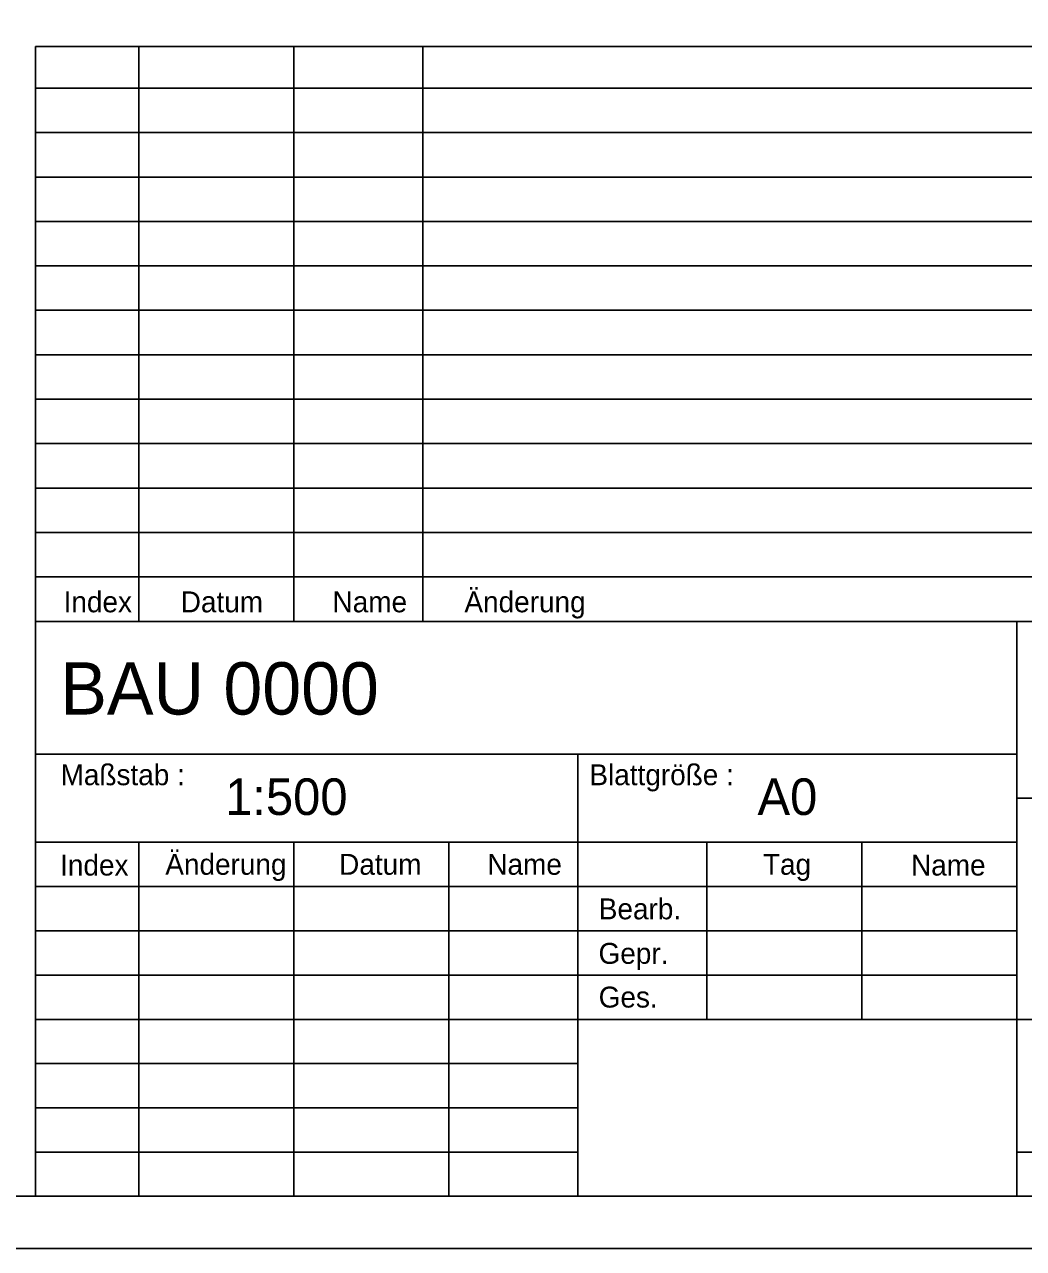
# Model space of a CAD drawing. Extents: x 0 to 594, y 0 to 420.
# Drawn here: x 502.5 to 550.3, y 0 to 58.5 of the extents above; entities that cross this region are included whole.
import ezdxf

# ---------------------------------------------------------------- set-up
doc = ezdxf.new("R2010")
doc.units = 0
doc.layers.add('90_Plankopf', color=7, linetype='Continuous')

msp = doc.modelspace()

# ---------------------------------------------------------------- linework, layer by layer
at = {"layer": '90_Plankopf'}
for p, q in [((503.06, 29.995), (503.06, 57.49)), ((503.06, 57.49), (592, 57.49)), ((508.001, 29.995), (508.001, 57.49)), ((515.413, 29.995), (515.413, 57.49)), ((521.59, 29.995), (521.59, 57.49)), ((503.06, 55.495), (592, 55.495)), ((503.06, 53.37), (592, 53.37)), ((503.06, 51.245), (592, 51.245)), ((503.06, 49.12), (592, 49.12)), ((503.06, 46.995), (592, 46.995)), ((503.06, 44.87), (592, 44.87)), ((503.06, 42.745), (592, 42.745)), ((503.06, 40.62), (592, 40.62)), ((503.06, 38.495), (592, 38.495)), ((503.06, 36.37), (592, 36.37)), ((503.06, 34.245), (592, 34.245)), ((503.06, 32.12), (592, 32.12)), ((503.06, 29.995), (592, 29.995)), ((503.06, 2.5), (503.06, 29.995)), ((503.06, 29.995), (592, 29.995)), ((550, 2.5), (550, 29.995)), ((503.06, 23.65), (550, 23.65)), ((529.001, 2.5), (529.001, 23.65)), ((550, 21.535), (592, 21.535)), ((503.06, 19.435), (550, 19.435)), ((508.001, 19.42), (508.001, 2.5)), ((515.413, 2.5), (515.413, 19.42)), ((522.825, 2.5), (522.825, 19.42)), ((535.177, 19.42), (535.177, 10.96)), ((542.589, 10.96), (542.589, 19.42)), ((503.06, 17.315), (550, 17.315)), ((503.06, 15.19), (550, 15.19)), ((503.06, 13.075), (550, 13.075)), ((503.06, 10.96), (550, 10.96)), ((503.06, 10.96), (550, 10.96)), ((529.001, 10.96), (550, 10.96)), ((550, 10.96), (592, 10.96)), ((529.001, 8.845), (503.06, 8.845)), ((529.001, 6.73), (503.06, 6.73)), ((503.06, 4.615), (529.001, 4.615)), ((550, 4.615), (592, 4.615)), ((592, 2.5), (503.06, 2.5)), ((503.06, 2.5), (529.001, 2.5)), ((508.9, 2.5), (592, 2.5)), ((508.9, 2.5), (592, 2.5))]:
    msp.add_line(p, q, dxfattribs=at)
for points in [[(0, 0), (594.5, 0), (594.5, 420.5), (0, 420.5)], [(12.5, 2.5), (592, 2.5), (592, 418), (12.5, 418)]]:
    msp.add_lwpolyline(points, close=True, dxfattribs=at)

# ---------------------------------------------------------------- texts
for s, height, p in [('Änderung', 1, (523.579, 30.428)), ('Index', 1, (504.402, 30.428)), ('Datum', 1, (510.007, 30.428)), ('Name', 1, (517.269, 30.428)), ('BAU 0000      ', 2.5, (504.245, 25.538)), ('Maßstab :', 1, (504.258, 22.158)), ('Blattgröße :', 0.99995, (529.558, 22.158)), ('1:500    ', 1.75, (512.131, 20.734)), ('A0       ', 1.75, (537.6, 20.734)), ('Index', 1, (504.235, 17.837)), ('Änderung', 1, (509.267, 17.875)), ('Datum', 1, (517.584, 17.875)), ('Name', 1, (524.673, 17.875)), ('Tag', 1, (537.861, 17.875)), ('Name', 1, (544.946, 17.837)), ('Bearb.', 1, (530.007, 15.745)), ('Gepr.', 1, (529.995, 13.615)), ('Ges.', 1, (530.002, 11.524))]:
    msp.add_text(s, height=height, dxfattribs=at).set_placement(p)

doc.saveas('drawing.dxf')
